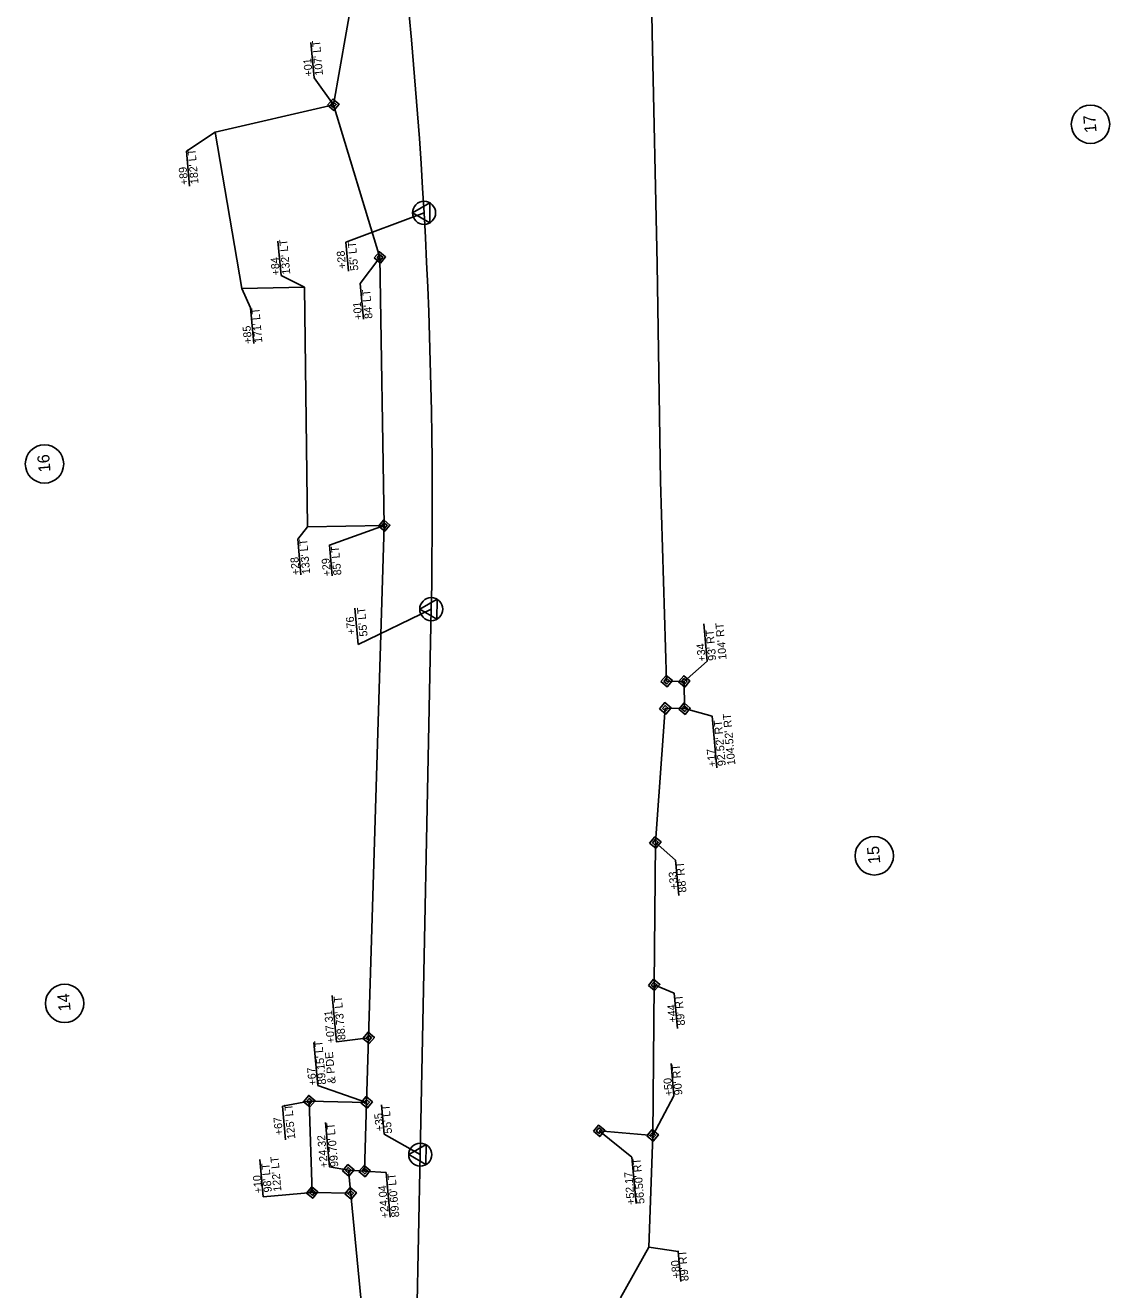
# Model space of a CAD drawing. Extents: x 1555582 to 1558054, y 687961 to 694065.
# Drawn here: x 1555856 to 1556534, y 691713 to 692503 of the extents above; entities that cross this region are included whole.
import ezdxf

# ---------------------------------------------------------------- set-up
doc = ezdxf.new("R2010")
doc.units = 0
for name, color, linetype in [('Exist Horizontal Alignment', 7, 'Continuous'), ('Exist Hydrographic FEMA Cross Section', 7, 'Continuous'), ('Exist Structure Major Bridge Seam', 7, 'Continuous'), ('Exist Structure Minor Drop Inlet Text', 7, 'Continuous'), ('Prop Approach Slab', 7, 'Continuous'), ('Prop Approach Slab Hatching', 7, 'Continuous'), ('Prop Boundary Easement Temporary Drainage Label', 7, 'Continuous'), ('Prop Drainage Structure Box Reinforced Concrete', 7, 'Continuous'), ('Prop Drainage Structure Catch Basin Grate 840 03F Label', 7, 'Continuous'), ('Prop Drainage Structure Catch Basin Grate 840 03G CELL', 7, 'Continuous'), ('Prop Drainage Structure Plot Symbol 50 Scale', 7, 'Continuous'), ('Prop Erosion Rip Rap Class II', 7, 'Continuous'), ('Prop Plan Preparation Excavation Hatching', 7, 'Continuous'), ('Scratch_Level_3', 7, 'Continuous')]:
    doc.layers.add(name, color=color, linetype=linetype)

msp = doc.modelspace()

# ---------------------------------------------------------------- linework, layer by layer
at = {"layer": 'Exist Horizontal Alignment'}
for p, q in [((1556056.18, 692367.42), (1556057.81, 692349.26)), ((1556061.92, 692138.79), (1556063.98, 692115.94)), ((1556078.45, 691828.2), (1556080.08, 691810.04))]:
    msp.add_line(p, q, dxfattribs=at)
for points in [[(1556056.18, 692367.42), (1556105.08, 692385.79)], [(1556063.98, 692115.94), (1556109.56, 692138.09)], [(1556080.08, 691810.04), (1556102.69, 691797.16)]]:
    msp.add_lwpolyline(points, dxfattribs=at)
at = {"layer": 'Exist Hydrographic FEMA Cross Section'}
for p, q in [((1556102.69, 691797.16), (1556109.56, 692138.09)), ((1556095.82, 691456.22), (1556102.69, 691797.16))]:
    msp.add_line(p, q, dxfattribs=at)
msp.add_arc((1552867.37, 692203.31), 3242.85, 358.84759, 7.60403, dxfattribs=at)
at = {"layer": 'Exist Structure Major Bridge Seam'}
for p, q in [((1556036.18, 691867.32), (1556038.61, 691840.3)), ((1556038.61, 691840.3), (1556069.19, 691829.85)), ((1556016.56, 691827.41), (1556018.44, 691806.51)), ((1556002.43, 691794.24), (1556004.54, 691770.78))]:
    msp.add_line(p, q, dxfattribs=at)
for points in [[(1556016.56, 691827.41), (1556033.35, 691830.57)], [(1556004.54, 691770.78), (1556035.2, 691773.52)]]:
    msp.add_lwpolyline(points, dxfattribs=at)
at = {"layer": 'Exist Structure Minor Drop Inlet Text'}
for p, q in [((1555956.55, 692424.38), (1555974.5, 692436.15)), ((1555956.55, 692424.38), (1555958.53, 692402.38)), ((1556263.82, 691736.64), (1556265.51, 691717.89))]:
    msp.add_line(p, q, dxfattribs=at)
for points in [[(1556013.77, 692368.16), (1556015.71, 692346.64), (1556030.29, 692339.27)], [(1555998.69, 692304.12), (1555996.68, 692326.46), (1555991.29, 692338.54)], [(1556028.14, 692159.55), (1556026.13, 692181.89), (1556032.18, 692189.56)], [(1556263.82, 691736.64), (1556245.55, 691739.27)]]:
    msp.add_lwpolyline(points, dxfattribs=at)
at = {"layer": 'Prop Approach Slab'}
for p, q in [((1556048.4, 692453.34), (1556062.99, 692535.58)), ((1556077.49, 692357.88), (1556048.4, 692453.34)), ((1556080.19, 692190.32), (1556077.49, 692357.88)), ((1556070.42, 691870.14), (1556080.19, 692190.32)), ((1556069.19, 691829.85), (1556070.42, 691870.14)), ((1556067.88, 691786.91), (1556069.19, 691829.85)), ((1556069.96, 691661.8), (1556057.79, 691787.39)), ((1556057.79, 691787.39), (1556067.88, 691786.91))]:
    msp.add_line(p, q, dxfattribs=at)
at = {"layer": 'Prop Approach Slab Hatching'}
for p, q in [((1556048.4, 692453.34), (1556048.4, 692453.34)), ((1556077.49, 692357.88), (1556077.49, 692357.88)), ((1556080.19, 692190.32), (1556080.19, 692190.32)), ((1556256.69, 692093.12), (1556256.69, 692093.12)), ((1556267.68, 692092.9), (1556267.68, 692092.9)), ((1556255.86, 692076.15), (1556255.86, 692076.15)), ((1556267.86, 692075.91), (1556267.86, 692075.91)), ((1556249.65, 691992.24), (1556249.65, 691992.24)), ((1556248.86, 691903.24), (1556248.86, 691903.24)), ((1556070.42, 691870.14), (1556070.42, 691870.14)), ((1556033.35, 691830.57), (1556033.35, 691830.57)), ((1556069.19, 691829.85), (1556069.19, 691829.85)), ((1556214.52, 691812.09), (1556214.52, 691812.09)), ((1556247.96, 691809.24), (1556247.96, 691809.24)), ((1556057.79, 691787.39), (1556057.79, 691787.39)), ((1556067.88, 691786.91), (1556067.88, 691786.91)), ((1556035.2, 691773.52), (1556035.2, 691773.52)), ((1556059.18, 691773.04), (1556059.18, 691773.04))]:
    msp.add_line(p, q, dxfattribs=at)
at = {"layer": 'Prop Boundary Easement Temporary Drainage Label'}
for p, q in [((1556081.41, 691786.07), (1556067.88, 691786.91)), ((1556083.92, 691758.18), (1556081.41, 691786.07))]:
    msp.add_line(p, q, dxfattribs=at)
for points in [[(1556034.37, 692492.21), (1556036.35, 692470.21), (1556048.4, 692453.34)], [(1556067.22, 692319.26), (1556065.21, 692341.6), (1556077.49, 692357.88)], [(1556047.68, 692158.97), (1556045.96, 692178.09), (1556080.19, 692190.32)], [(1556047.71, 691896.66), (1556050.31, 691867.78), (1556070.42, 691870.14)], [(1556043.48, 691817.36), (1556045.99, 691789.48), (1556057.79, 691787.39)]]:
    msp.add_lwpolyline(points, dxfattribs=at)
at = {"layer": 'Prop Drainage Structure Box Reinforced Concrete'}
for p, q in [((1556245.55, 691739.27), (1556247.96, 691809.24)), ((1556227.91, 691707.62), (1556245.55, 691739.27))]:
    msp.add_line(p, q, dxfattribs=at)
msp.add_lwpolyline([(1556080.19, 692190.32), (1556032.18, 692189.56), (1556030.29, 692339.27), (1555991.29, 692338.54), (1555974.5, 692436.15), (1556048.4, 692453.34)], dxfattribs=at)
at = {"layer": 'Prop Drainage Structure Catch Basin Grate 840 03F Label'}
for p, q in [((1556521.58, 692441.14), (1556521.58, 692441.14)), ((1555867.87, 692228.83), (1555867.87, 692228.83)), ((1556386.44, 691983.94), (1556386.44, 691983.94)), ((1555880.46, 691891.69), (1555880.46, 691891.69))]:
    msp.add_line(p, q, dxfattribs=at)
for centre in [(1556521.58, 692441.14), (1555867.87, 692228.83), (1556386.44, 691983.94), (1555880.46, 691891.69)]:
    msp.add_circle(centre, 12, dxfattribs=at)
at = {"layer": 'Prop Drainage Structure Plot Symbol 50 Scale'}
for p, q in [((1556105.08, 692385.79), (1556105.08, 692385.79)), ((1556109.56, 692138.09), (1556109.56, 692138.09)), ((1556279.88, 692128.85), (1556281.97, 692105.58)), ((1556285.16, 692071.31), (1556267.86, 692075.91)), ((1556285.16, 692071.31), (1556288.07, 692038.97)), ((1556262.24, 691981.17), (1556264.23, 691959.1)), ((1556261.39, 691898.03), (1556263.37, 691875.97)), ((1556261.25, 691834.02), (1556259.44, 691854.18)), ((1556261.25, 691834.02), (1556247.96, 691809.24)), ((1556102.69, 691797.16), (1556102.69, 691797.16)), ((1556235.01, 691795.53), (1556237.61, 691766.65))]:
    msp.add_line(p, q, dxfattribs=at)
for points in [[(1556108.67, 692379.54), (1556097.88, 692385.8), (1556108.69, 692392.04)], [(1556113.15, 692131.84), (1556102.36, 692138.1), (1556113.17, 692144.34)], [(1556106.28, 691790.91), (1556095.49, 691797.17), (1556106.3, 691803.41)]]:
    msp.add_lwpolyline(points, close=True, dxfattribs=at)
for points in [[(1556281.97, 692105.58), (1556267.68, 692092.9)], [(1556262.24, 691981.17), (1556249.65, 691992.24)], [(1556261.39, 691898.03), (1556248.86, 691903.24)], [(1556235.01, 691795.53), (1556214.52, 691812.09)]]:
    msp.add_lwpolyline(points, dxfattribs=at)
for centre in [(1556105.08, 692385.79), (1556109.56, 692138.09), (1556102.69, 691797.16)]:
    msp.add_circle(centre, 7.2, dxfattribs=at)
at = {"layer": 'Prop Erosion Rip Rap Class II'}
for p, q in [((1556033.35, 691830.57), (1556069.19, 691829.85)), ((1556035.2, 691773.52), (1556033.35, 691830.57)), ((1556059.18, 691773.04), (1556035.2, 691773.52))]:
    msp.add_line(p, q, dxfattribs=at)
at = {"layer": 'Prop Plan Preparation Excavation Hatching'}
for p, q in [((1556267.68, 692092.9), (1556256.69, 692093.12)), ((1556267.86, 692075.91), (1556267.68, 692092.9)), ((1556249.65, 691992.24), (1556255.86, 692076.15)), ((1556255.86, 692076.15), (1556267.86, 692075.91)), ((1556248.86, 691903.24), (1556249.65, 691992.24)), ((1556247.96, 691809.24), (1556248.86, 691903.24)), ((1556214.52, 691812.09), (1556247.96, 691809.24))]:
    msp.add_line(p, q, dxfattribs=at)
msp.add_lwpolyline([(1556256.69, 692093.12), (1556252.85, 692218.06), (1556250.77, 692353.77), (1556247.71, 692498.34), (1556245.63, 692618.36)], dxfattribs=at)
at = {"layer": 'Scratch_Level_3'}
for points in [[(1556044.82, 692453.01), (1556048.08, 692456.92), (1556051.99, 692453.66), (1556048.72, 692449.75)], [(1556046.61, 692453.17), (1556048.24, 692455.13), (1556050.19, 692453.5), (1556048.56, 692451.54)], [(1556073.91, 692357.56), (1556077.17, 692361.47), (1556081.08, 692358.2), (1556077.81, 692354.3)], [(1556075.7, 692357.72), (1556077.33, 692359.67), (1556079.28, 692358.04), (1556077.65, 692356.09)], [(1556076.6, 692190), (1556079.87, 692193.91), (1556083.77, 692190.65), (1556080.51, 692186.74)], [(1556078.4, 692190.16), (1556080.03, 692192.12), (1556081.98, 692190.48), (1556080.35, 692188.53)], [(1556253.1, 692092.8), (1556256.36, 692096.71), (1556260.27, 692093.44), (1556257.01, 692089.54)], [(1556254.89, 692092.96), (1556256.52, 692094.91), (1556258.48, 692093.28), (1556256.85, 692091.33)], [(1556264.1, 692092.58), (1556267.36, 692096.49), (1556271.27, 692093.22), (1556268.01, 692089.32)], [(1556265.89, 692092.74), (1556267.52, 692094.69), (1556269.48, 692093.06), (1556267.84, 692091.11)], [(1556252.27, 692075.83), (1556255.54, 692079.73), (1556259.44, 692076.47), (1556256.18, 692072.56)], [(1556254.07, 692075.99), (1556255.7, 692077.94), (1556257.65, 692076.31), (1556256.02, 692074.36)], [(1556264.27, 692075.58), (1556267.54, 692079.49), (1556271.44, 692076.23), (1556268.18, 692072.32)], [(1556266.06, 692075.75), (1556267.7, 692077.7), (1556269.65, 692076.07), (1556268.02, 692074.11)], [(1556246.07, 691991.92), (1556249.33, 691995.83), (1556253.24, 691992.57), (1556249.97, 691988.66)], [(1556247.86, 691992.08), (1556249.49, 691994.04), (1556251.44, 691992.4), (1556249.81, 691990.45)], [(1556245.27, 691902.92), (1556248.54, 691906.83), (1556252.44, 691903.56), (1556249.18, 691899.66)], [(1556247.07, 691903.08), (1556248.7, 691905.03), (1556250.65, 691903.4), (1556249.02, 691901.45)], [(1556066.84, 691869.81), (1556070.1, 691873.72), (1556074.01, 691870.46), (1556070.74, 691866.55)], [(1556068.63, 691869.98), (1556070.26, 691871.93), (1556072.21, 691870.3), (1556070.58, 691868.34)], [(1556029.77, 691830.25), (1556033.03, 691834.15), (1556036.94, 691830.89), (1556033.67, 691826.98)], [(1556065.61, 691829.52), (1556068.87, 691833.43), (1556072.78, 691830.17), (1556069.52, 691826.26)], [(1556031.56, 691830.41), (1556033.19, 691832.36), (1556035.14, 691830.73), (1556033.51, 691828.78)], [(1556067.4, 691829.68), (1556069.03, 691831.64), (1556070.98, 691830.01), (1556069.35, 691828.05)], [(1556210.93, 691811.77), (1556214.19, 691815.67), (1556218.1, 691812.41), (1556214.84, 691808.5)], [(1556212.72, 691811.93), (1556214.36, 691813.88), (1556216.31, 691812.25), (1556214.68, 691810.3)], [(1556244.38, 691808.92), (1556247.64, 691812.83), (1556251.55, 691809.56), (1556248.29, 691805.65)], [(1556246.17, 691809.08), (1556247.8, 691811.03), (1556249.76, 691809.4), (1556248.13, 691807.45)], [(1556054.2, 691787.07), (1556057.46, 691790.97), (1556061.37, 691787.71), (1556058.11, 691783.8)], [(1556055.99, 691787.23), (1556057.63, 691789.18), (1556059.58, 691787.55), (1556057.95, 691785.6)], [(1556064.3, 691786.59), (1556067.56, 691790.49), (1556071.47, 691787.23), (1556068.21, 691783.32)], [(1556066.09, 691786.75), (1556067.72, 691788.7), (1556069.67, 691787.07), (1556068.04, 691785.12)], [(1556031.62, 691773.2), (1556034.88, 691777.1), (1556038.79, 691773.84), (1556035.52, 691769.93)], [(1556033.41, 691773.36), (1556035.04, 691775.31), (1556036.99, 691773.68), (1556035.36, 691771.73)], [(1556055.59, 691772.71), (1556058.86, 691776.62), (1556062.76, 691773.36), (1556059.5, 691769.45)], [(1556057.39, 691772.87), (1556059.02, 691774.83), (1556060.97, 691773.2), (1556059.34, 691771.24)]]:
    msp.add_lwpolyline(points, close=True, dxfattribs=at)

# ---------------------------------------------------------------- texts
at = {"layer": 'Exist Horizontal Alignment'}
for s, p in [("55' LT", (1556064.04, 692349.8)), ('+28', (1556056.4, 692351.03)), ('+76', (1556062.14, 692122.42)), ("55' LT", (1556069.78, 692121.17)), ("55' LT", (1556085.09, 691810.47)), ('+35', (1556079.88, 691812.02))]:
    msp.add_text(s, height=5, rotation=95.14143, dxfattribs=at).set_placement(p)
at = {"layer": 'Exist Structure Major Bridge Seam'}
for s, p in [("89.15' LT", (1556043.9, 691841.15)), ('& PDE', (1556049.88, 691841.69)), ('+67', (1556037.93, 691840.61)), ("125' LT", (1556024.67, 691807.05)), ('+67', (1556016.92, 691809.54)), ("122' LT", (1556015.98, 691774.33)), ("98' LT", (1556010, 691773.79)), ('+10', (1556004.03, 691773.25))]:
    msp.add_text(s, height=5, rotation=95.14143, dxfattribs=at).set_placement(p)
at = {"layer": 'Exist Structure Minor Drop Inlet Text'}
for s, p in [("182' LT", (1555964.16, 692403.99)), ('+89', (1555957.68, 692403.41)), ("132' LT", (1556021.51, 692347.47)), ('+84', (1556015.03, 692346.89)), ("171' LT", (1556004.07, 692304.73)), ('+85', (1555997.59, 692304.15)), ("133' LT", (1556033.94, 692160.18)), ('+28', (1556027.47, 692159.6)), ('+80', (1556265.29, 691720.07)), ("89' RT", (1556270.51, 691718.32))]:
    msp.add_text(s, height=5, rotation=95.14143, dxfattribs=at).set_placement(p)
at = {"layer": 'Prop Boundary Easement Temporary Drainage Label'}
for s, p in [("107' LT", (1556041.97, 692471.82)), ('+01', (1556035.5, 692471.24)), ("84' LT", (1556072.94, 692319.77)), ('+01', (1556066.47, 692319.19)), ("85' LT", (1556053.46, 692159.45)), ('+29', (1556046.99, 692158.87)), ("88.73' LT", (1556056.08, 691868.96)), ('+07.31', (1556049.41, 691867)), ('+24.32', (1556045.04, 691789.11)), ("99.70' LT", (1556051.52, 691789.69)), ('+24.04', (1556083.18, 691757.62)), ("89.60' LT", (1556089.65, 691758.2))]:
    msp.add_text(s, height=5, rotation=95.14143, dxfattribs=at).set_placement(p)
at = {"layer": 'Prop Drainage Structure Catch Basin Grate 840 03G CELL'}
for s, p in [('17', (1556525.43, 692436.13)), ('16', (1555871.71, 692224.01)), ('15', (1556390.26, 691979.24)), ('14', (1555884.27, 691887.05))]:
    msp.add_text(s, height=7.5, rotation=95.14143, dxfattribs=at).set_placement(p)
at = {"layer": 'Prop Drainage Structure Plot Symbol 50 Scale'}
for s, p in [("104' RT", (1556294.17, 692106.68)), ("93' RT ", (1556287.7, 692106.1)), ('+34', (1556281.23, 692105.51)), ("104.52' RT", (1556299.66, 692040.79)), ("92.52' RT ", (1556293.68, 692040.25)), ('+17', (1556287.7, 692039.71)), ("88' RT ", (1556269.09, 691961.19)), ('+33', (1556263.85, 691963.04)), ("89' RT ", (1556268.23, 691878.05)), ('+44', (1556262.99, 691879.94)), ("90' RT ", (1556266.59, 691834.54)), ('+50', (1556260.61, 691834)), ("56.50' RT ", (1556242.91, 691766.6)), ('+52.17', (1556236.93, 691766.06))]:
    msp.add_text(s, height=5, rotation=95.14143, dxfattribs=at).set_placement(p)

doc.saveas('drawing.dxf')
